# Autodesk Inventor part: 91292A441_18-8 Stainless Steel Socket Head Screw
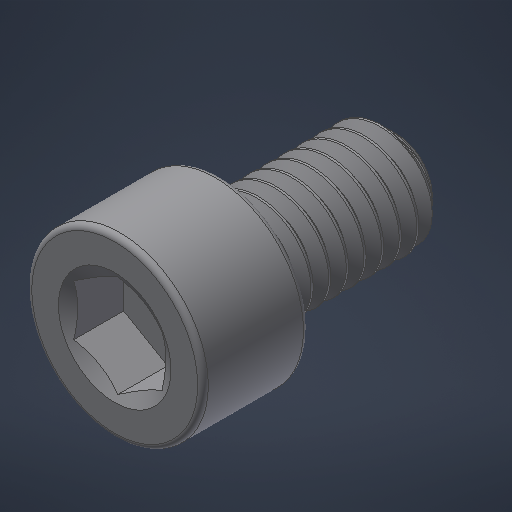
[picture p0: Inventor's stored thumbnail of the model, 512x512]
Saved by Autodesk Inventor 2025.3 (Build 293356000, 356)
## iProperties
Created: 2026-02
Part Number: 91292A441_18-8 Stainless Steel Socket Head Screw
Project: COMMON
Material: Generic
Catalog Web Link: https://www.janelia.org/
Vendor: HHMI: JRC - JET
Document SubType Name: Modeling
Designer: sohna
Density: 1 g/cm^3
Appearance: Default
RuleStatus: InUse
AfterDocSave0: file://Part Number Cleaner
Title: Standard
Author: sohna
Revision Number: 0
LAB/DEPT: COMMON
REQUESTING SCIENTIST: COMMON
DESIGN DEPARTMENT: HHMI: JRC - ID&F
ALTERED ITEM PART NUMBER: N/A
ALTERED ITEM VENDOR: N/A
ALTERED ITEM DESCRIPTION: N/A
Revision: ANY
Author: McMaster Carr Supply
Title: 91292A441_18-8 Stainless Steel Socket Head Screw.STEP
Organization: McMaster Carr Supply
Description: STEP AP203
Sending System: SolidWorks 2024
Preprocessor: SwSTEP 2.0
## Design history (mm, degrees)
feature "Boss-Extrude1"
body "Solid1"
